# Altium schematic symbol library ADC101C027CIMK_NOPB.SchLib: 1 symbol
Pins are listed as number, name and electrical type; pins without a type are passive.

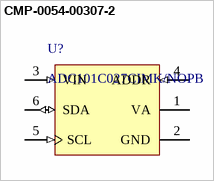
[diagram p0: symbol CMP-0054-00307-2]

## CMP-0054-00307-2
designator U?, comment ADC101C027CIMK/NOPB
I2C-Compatible, 10-Bit Analog-to-Digital Converter (ADC) with Alert Function, 6-pin Tiny SOT23, Pb-Free; Manufacturer: National Semiconductor; PowerWise: N; PackageTopMarking: X32C*XTT; CompType: ADC IC
footprint MK06A_L (SOT23, 6-Leads, Body 3.0x1.7mm, Pitch 0.95mm, Lead Span 2.9mm, IPC High Density)
footprint MK06A_N (SOT23, 6-Leads, Body 3.0x1.7mm, Pitch 0.95mm, Lead Span 2.9mm, IPC Medium Density)
footprint MK06A_M (SOT23, 6-Leads, Body 3.0x1.7mm, Pitch 0.95mm, Lead Span 2.9mm, IPC Low Density)
pins: 1 VA (power), 2 GND (power), 3 VIN (in), 4 ADDR (in), 5 SCL (in), 6 SDA (io)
